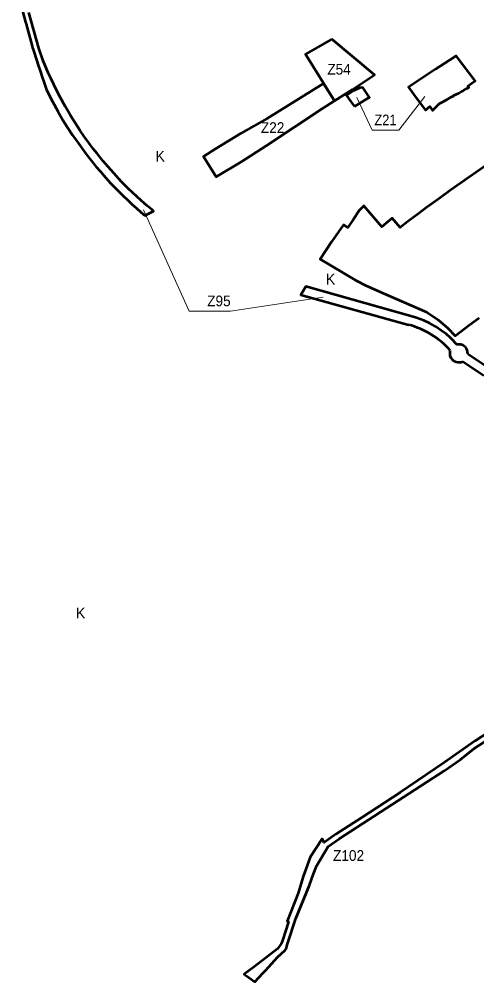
# Model space of a CAD drawing. Extents: x -650246 to -642674, y -1074280 to -1066767.
# Drawn here: x -649069 to -648043, y -1072846 to -1070690 of the extents above; entities that cross this region are included whole.
import ezdxf

# ---------------------------------------------------------------- set-up
doc = ezdxf.new("R2010")
doc.units = 0
doc.header["$LTSCALE"] = 9.6
for name, color, linetype, lineweight in [('42', 7, 'Continuous', 25), ('44', 7, 'Continuous', 53), ('45', 7, 'Continuous', 53), ('46', 7, 'Continuous', 13), ('48', 7, 'Continuous', 13)]:
    doc.layers.add(name, color=color, linetype=linetype, lineweight=lineweight)

msp = doc.modelspace()

# ---------------------------------------------------------------- linework, layer by layer
at = {"layer": '42'}
msp.add_lwpolyline([(-648386.587, -1070833.807), (-648512.981, -1070911.776), (-648571.14, -1070944.67), (-648628.712, -1070979.892), (-648655.76, -1070997.5), (-648627.39, -1071042.65), (-648570.23, -1071008.2), (-648515.46, -1070972.94), (-648389.33, -1070889.79), (-648362.519, -1070872.788)], close=True, dxfattribs=at)
at = {"layer": '44'}
for points in [[(-649068.65, -1070642.23), (-649054.31, -1070696.44), (-649052.77, -1070702.25), (-649052.44, -1070703.48), (-649051.03, -1070708.74), (-649040.03, -1070750.06), (-649039.38, -1070752.51), (-649039.06, -1070753.72), (-649038.51, -1070755.38), (-649027.74, -1070787.51), (-649027.64, -1070787.8), (-649019.48, -1070812.18), (-649018.48, -1070815.18), (-649011.24, -1070836.79), (-649010.67, -1070838.5), (-649007.885, -1070848.153), (-648994.464, -1070873.974), (-648982.467, -1070895.704), (-648970.712, -1070915.663), (-648960.268, -1070932.429), (-648949.389, -1070949.031), (-648939.232, -1070963.818), (-648918.601, -1070991.969), (-648896.068, -1071020.184), (-648886.874, -1071031.044), (-648874.793, -1071044.773), (-648863.847, -1071056.723), (-648851.175, -1071069.886), (-648838.696, -1071082.562), (-648823.087, -1071097.562), (-648816.379, -1071103.782), (-648806.239, -1071112.938), (-648797, -1071121), (-648790.23, -1071126.818), (-648787.207, -1071129.363), (-648767.824, -1071119.455), (-648771.725, -1071116.233), (-648781.806, -1071107.721), (-648795.407, -1071095.8), (-648824.292, -1071068.677), (-648839.273, -1071053.556), (-648856.883, -1071034.761), (-648869.629, -1071020.411), (-648880.44, -1071007.703), (-648894.164, -1070990.806), (-648902.714, -1070979.812), (-648912.396, -1070966.893), (-648922.92, -1070952.242), (-648932.78, -1070937.887), (-648943.414, -1070921.659), (-648953.605, -1070905.299), (-648965.093, -1070885.794), (-648976.834, -1070864.527), (-648985.145, -1070848.538), (-648991.386, -1070835.954), (-648998.132, -1070821.723), (-649003.641, -1070809.566), (-649014.888, -1070782.994), (-649025.129, -1070754.377), (-649047.11, -1070674.743)], [(-648079.109, -1071418.563), (-648082.391, -1071418.063), (-648085.477, -1071418.086), (-648087.928, -1071418.446), (-648100.438, -1071405.517), (-648103.268, -1071402.88), (-648111.646, -1071395.618), (-648123.313, -1071386.696), (-648136.263, -1071378.194), (-648149.571, -1071370.788), (-648162.084, -1071364.918), (-648178.158, -1071358.781), (-648191.25, -1071354.858), (-648426.18, -1071288.32), (-648437.454, -1071306.778), (-648196.236, -1071374.226)], [(-648069.022, -1071424.443), (-648074.341, -1071420.189), (-648079.108, -1071418.564), (-648079.109, -1071418.563)], [(-648063.593, -1071439.723), (-648063.862, -1071435.078), (-648064.838, -1071431.28), (-648066.623, -1071427.592), (-648069.022, -1071424.443)], [(-648103.894, -1071436.836), (-648103.478, -1071442.736), (-648101.203, -1071448.31)], [(-648016.446, -1071471.268), (-648063.593, -1071439.723)], [(-648101.203, -1071448.31), (-648098.259, -1071452.196), (-648096.014, -1071454.192), (-648093.059, -1071456.066), (-648089.539, -1071457.489), (-648085.585, -1071458.248), (-648081.642, -1071458.215), (-648078.539, -1071457.636), (-648074.86, -1071456.248)], [(-648074.86, -1071456.248), (-648027.562, -1071487.894)], [(-647942.21, -1072238.54), (-648046.69, -1072306.3), (-648117.12, -1072356), (-648214.73, -1072422.41), (-648300.98, -1072478.1), (-648359.61, -1072515.85), (-648385.28, -1072534.41), (-648389.69, -1072526.36), (-648416.41, -1072567.43), (-648432.45, -1072610.56), (-648443.77, -1072648.02), (-648468.01, -1072710.44), (-648465.25, -1072712.03), (-648478.58, -1072753.49), (-648481.62, -1072761.39), (-648489.76, -1072772.74), (-648506.1, -1072785.56), (-648542.43, -1072812.6), (-648564.86, -1072829.45), (-648561.69, -1072831.54), (-648554.22, -1072836.89), (-648541.102, -1072846.281), (-648522.66, -1072826.92), (-648516.44, -1072820.39), (-648489.69, -1072791.37), (-648473.13, -1072775.58), (-648470.89, -1072772.42), (-648467.286, -1072761.426), (-648448.58, -1072704.37), (-648436.75, -1072675.79), (-648418.45, -1072629.91), (-648409.08, -1072604.25), (-648401.91, -1072586.1), (-648376.47, -1072543.52), (-648351.83, -1072525.81), (-648232.86, -1072449.45), (-648116.32, -1072373.44), (-648079.76, -1072348.46), (-648049.33, -1072323.77), (-647946.88, -1072257.82)]]:
    msp.add_lwpolyline(points, dxfattribs=at)
at = {"layer": '44', "lineweight": 13}
msp.add_lwpolyline([(-648790.074, -1071116.496), (-648687.825, -1071343.817), (-648595.588, -1071343.817), (-648387.63, -1071312.498)], dxfattribs=at)
at = {"layer": '44'}
for centre, radius, start, end in [((-648244.965, -1071557.871), 190, 41.59858, 75.1393), ((-648083.781, -1071438.172), 20.157, 161.35794, 176.20098)]:
    msp.add_arc(centre, radius, start, end, dxfattribs=at)
at = {"layer": '45'}
for points in [[(-648368.163, -1070734.376), (-648427.25, -1070767.95), (-648362.519, -1070872.788), (-648322.17, -1070847.2), (-648272.45, -1070814.075)], [(-648368.163, -1070734.376), (-648427.25, -1070767.95), (-648362.519, -1070872.788), (-648322.17, -1070847.2), (-648272.45, -1070814.075)], [(-648317.14, -1070885.48), (-648285.72, -1070865.96), (-648284.02, -1070864.91), (-648298.78, -1070842.92), (-648305.33, -1070843.62), (-648320.02, -1070850.16), (-648335.19, -1070860.49), (-648326.41, -1070873.55)], [(-648317.14, -1070885.48), (-648285.72, -1070865.96), (-648284.02, -1070864.91), (-648298.78, -1070842.92), (-648305.33, -1070843.62), (-648320.02, -1070850.16), (-648335.19, -1070860.49), (-648326.41, -1070873.55)]]:
    msp.add_lwpolyline(points, close=True, dxfattribs=at)
for points in [[(-648095.42, -1070860.3), (-648083.65, -1070854.89), (-648076.73, -1070851.07), (-648074.41, -1070849.79), (-648072.59, -1070848.79), (-648065.35, -1070844.8), (-648061.52, -1070842.68), (-648063.76, -1070839.49), (-648056.61, -1070834.26), (-648047.17, -1070827.35), (-648089.27, -1070771.57), (-648104.78, -1070781.65), (-648114.77, -1070788.08), (-648125.2, -1070794.79), (-648136.08, -1070801.79)], [(-648095.42, -1070860.3), (-648083.65, -1070854.89), (-648076.73, -1070851.07), (-648074.41, -1070849.79), (-648072.59, -1070848.79), (-648065.35, -1070844.8), (-648061.52, -1070842.68), (-648063.76, -1070839.49), (-648056.61, -1070834.26), (-648047.17, -1070827.35), (-648089.27, -1070771.57), (-648104.78, -1070781.65), (-648114.77, -1070788.08), (-648125.2, -1070794.79), (-648136.08, -1070801.79)], [(-648136.08, -1070801.79), (-648151.77, -1070812.11), (-648167.6, -1070822.53), (-648196.65, -1070841.7), (-648181.75, -1070862.74), (-648158.58, -1070892.98), (-648148.34, -1070884.92), (-648142.79, -1070893.78), (-648133.14, -1070884.6), (-648127, -1070878.75), (-648122.72, -1070876.44), (-648111.24, -1070870.11), (-648099.85, -1070863.82), (-648094.9, -1070861.09), (-648095.42, -1070860.3)], [(-648136.08, -1070801.79), (-648151.77, -1070812.11), (-648167.6, -1070822.53), (-648196.65, -1070841.7), (-648181.75, -1070862.74), (-648158.58, -1070892.98), (-648148.34, -1070884.92), (-648142.79, -1070893.78), (-648133.14, -1070884.6), (-648127, -1070878.75), (-648122.72, -1070876.44), (-648111.24, -1070870.11), (-648099.85, -1070863.82), (-648094.9, -1070861.09), (-648095.42, -1070860.3)], [(-648386.587, -1070833.807), (-648512.981, -1070911.776), (-648571.14, -1070944.67), (-648628.712, -1070979.892), (-648655.76, -1070997.5), (-648627.39, -1071042.65), (-648570.23, -1071008.2), (-648515.46, -1070972.94), (-648389.33, -1070889.79)], [(-648386.587, -1070833.807), (-648512.981, -1070911.776), (-648571.14, -1070944.67), (-648628.712, -1070979.892), (-648655.76, -1070997.5), (-648627.39, -1071042.65), (-648570.23, -1071008.2), (-648515.46, -1070972.94), (-648389.33, -1070889.79)], [(-648389.33, -1070889.79), (-648362.519, -1070872.788), (-648386.587, -1070833.807)], [(-648389.33, -1070889.79), (-648362.519, -1070872.788), (-648386.587, -1070833.807)], [(-647913.45, -1070940.79), (-648062.53, -1071044.59), (-648102.55, -1071072.86), (-648125.53, -1071089.51), (-648141.12, -1071100.71), (-648155.77, -1071111.23), (-648172.48, -1071123.95), (-648197.57, -1071143.03), (-648215.08, -1071156.35), (-648232.8, -1071135.6), (-648245.49, -1071145.91), (-648256.04, -1071154.5), (-648278.39, -1071128.74), (-648296.34, -1071108.04), (-648307.33, -1071118.47), (-648319.77, -1071137.52), (-648330.78, -1071154.36), (-648332.354, -1071156.279), (-648341.943, -1071150.071), (-648347.949, -1071158.385), (-648369.33, -1071188.149), (-648394.087, -1071227.18), (-648315.127, -1071274.052), (-648292.406, -1071286.112), (-648246.752, -1071306.054), (-648155.113, -1071346.082), (-648130, -1071363), (-648109, -1071381), (-648091.92, -1071399.07), (-648060.01, -1071374.69), (-648038.18, -1071358.51)]]:
    msp.add_lwpolyline(points, dxfattribs=at)
at = {"layer": '46'}
msp.add_line((-648277.841, -1070938.322), (-648311.985, -1070865.23), dxfattribs=at)
msp.add_line((-648277.841, -1070938.322), (-648311.985, -1070865.23), dxfattribs=at)
msp.add_lwpolyline([(-648277.841, -1070938.322), (-648217.945, -1070938.322), (-648160.135, -1070863.066)], dxfattribs=at)
msp.add_lwpolyline([(-648277.841, -1070938.322), (-648217.945, -1070938.322), (-648160.135, -1070863.066)], dxfattribs=at)

# ---------------------------------------------------------------- texts
at = {"layer": '44', "width": 0.95}
for s, p in [('Z95', (-648647.497, -1071332.741)), ('Z102', (-648365.47, -1072575.389)), ('Z102', (-648365.47, -1072575.389))]:
    msp.add_text(s, height=24, dxfattribs=at).set_placement(p)
at = {"layer": '46'}
for s, width, p in [('Z54', 0.95, (-648378.37, -1070813.706)), ('Z54', 0.95, (-648378.37, -1070813.706)), ('Z21', 0.9, (-648272.998, -1070927.282)), ('Z21', 0.9, (-648272.998, -1070927.282)), ('Z22', 0.95, (-648527.125, -1070944.357)), ('Z22', 0.95, (-648527.125, -1070944.357))]:
    msp.add_text(s, height=24, dxfattribs=dict(at, width=width)).set_placement(p)
at = {"layer": '48'}
for p in [(-648763.558, -1071008.525), (-648763.558, -1071008.525), (-648382.039, -1071284.028), (-648941.849, -1072032.089), (-648941.849, -1072032.089)]:
    msp.add_text('K', height=24, dxfattribs=at).set_placement(p)

doc.saveas('drawing.dxf')
